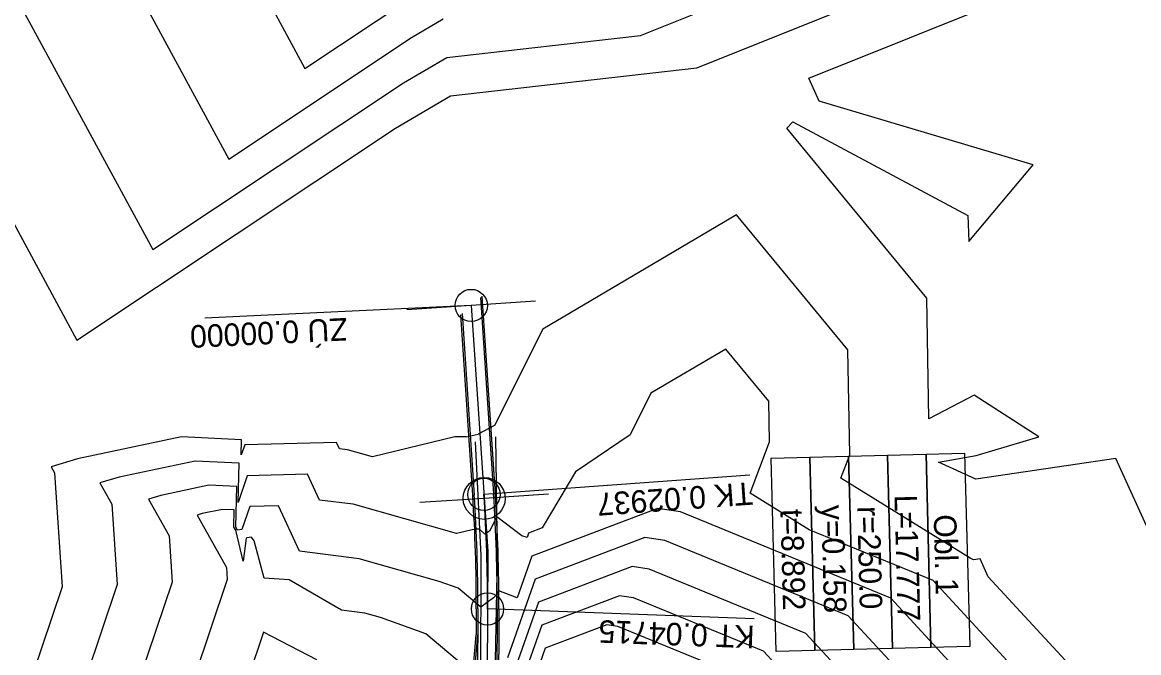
# Model space of a CAD drawing. Extents: x -549394 to -546608, y -1037055 to -1033629.
# Drawn here: x -547510.8 to -547337.6, y -1035891.5 to -1035793.8 of the extents above; entities that cross this region are included whole.
import ezdxf

# ---------------------------------------------------------------- set-up
doc = ezdxf.new("R2010")
doc.units = 0
for name, color, linetype in [('hlavni_vrst', 7, 'Continuous'), ('hrana_L', 7, 'Continuous'), ('norm_vrst', 7, 'Continuous'), ('POLYGONY_SITUACE_PO', 7, 'Continuous'), ('u_sirka_1_5m', 7, 'Continuous'), ('x_navrh_C41', 7, 'Continuous'), ('x_osa_C41', 7, 'Continuous'), ('x_popis_oblouky_C41', 7, 'Continuous'), ('x_popis_pricne_rezy_C41', 7, 'Continuous')]:
    doc.layers.add(name, color=color, linetype=linetype)

msp = doc.modelspace()

# ---------------------------------------------------------------- linework, layer by layer
at = {"layer": 'hlavni_vrst'}
for p, q in [((-547406.17, -1035800.86), (-547360.49, -1035782.56)), ((-547532.66, -1035787.02), (-547502.28, -1035843.08)), ((-547444.33, -1035805.2), (-547406.17, -1035800.86)), ((-547452.88, -1035810.18), (-547444.33, -1035805.2)), ((-547502.28, -1035843.08), (-547452.88, -1035810.18)), ((-547399.98, -1035823.64), (-547430.05, -1035841.36)), ((-547382.73, -1035844.56), (-547399.98, -1035823.64)), ((-547430.05, -1035841.36), (-547437.54, -1035856.34)), ((-547382.44, -1035860.87), (-547382.73, -1035844.56)), ((-547441.94, -1035858.1), (-547440.06, -1035857.66)), ((-547437.54, -1035856.34), (-547440.06, -1035857.66)), ((-547486.09, -1035858.1), (-547502.18, -1035861.49)), ((-547476.76, -1035858.54), (-547486.09, -1035858.1)), ((-547476.83, -1035860.89), (-547476.76, -1035858.54)), ((-547476.27, -1035859.29), (-547476.83, -1035860.89)), ((-547462.05, -1035858.96), (-547476.27, -1035859.29)), ((-547461.59, -1035859.93), (-547462.05, -1035858.96)), ((-547443.69, -1035858.08), (-547456.44, -1035861.2)), ((-547441.94, -1035858.1), (-547443.69, -1035858.08)), ((-547460.32, -1035860.09), (-547461.59, -1035859.93)), ((-547456.44, -1035861.2), (-547460.32, -1035860.09)), ((-547383.82, -1035864.47), (-547382.44, -1035860.87)), ((-547502.18, -1035861.49), (-547506.27, -1035862.72)), ((-547506.27, -1035862.72), (-547505.76, -1035863.64)), ((-547505.76, -1035863.64), (-547504.58, -1035881.36)), ((-547363.77, -1035876.89), (-547383.82, -1035864.47)), ((-547363.25, -1035877.13), (-547363.77, -1035876.89)), ((-547362.22, -1035876.97), (-547363.25, -1035877.13)), ((-547360.95, -1035879.77), (-547362.22, -1035876.97)), ((-547332, -1035911.09), (-547360.95, -1035879.77)), ((-547504.58, -1035881.36), (-547509.38, -1035895.62)), ((-547418.16, -1035882.71), (-547430.19, -1035887.28)), ((-547415.96, -1035883.04), (-547418.16, -1035882.71)), ((-547395.81, -1035891.3), (-547415.96, -1035883.04)), ((-547430.19, -1035887.28), (-547434.32, -1035898.99)), ((-547380.57, -1035907.78), (-547395.81, -1035891.3))]:
    msp.add_line(p, q, dxfattribs=at)
at = {"layer": 'hrana_L'}
for p, q in [((-547440.53, -1035858.83), (-547439.64, -1035876.54)), ((-547437.07, -1035876.65), (-547437.31, -1035858.07)), ((-547439.64, -1035876.54), (-547439.76, -1035904.44)), ((-547437.57, -1035904.54), (-547437.07, -1035876.65))]:
    msp.add_line(p, q, dxfattribs=at)
at = {"layer": 'norm_vrst'}
for p, q in [((-547557.48, -1035705.44), (-547490.5, -1035829.04)), ((-547531.65, -1035717.32), (-547478.72, -1035814.99)), ((-547500.19, -1035739.58), (-547466.93, -1035800.95)), ((-547414.88, -1035795.82), (-547378.94, -1035781.42)), ((-547388.81, -1035802.44), (-547342.04, -1035783.7)), ((-547466.93, -1035800.95), (-547449.13, -1035789.09)), ((-547450.38, -1035796.12), (-547445.48, -1035793.26)), ((-547478.72, -1035814.99), (-547450.38, -1035796.12)), ((-547444.91, -1035799.23), (-547414.88, -1035795.82)), ((-547451.63, -1035803.15), (-547444.91, -1035799.23)), ((-547387.2, -1035806.02), (-547388.81, -1035802.44)), ((-547490.5, -1035829.04), (-547451.63, -1035803.15)), ((-547354.01, -1035815.88), (-547387.2, -1035806.02)), ((-547392.21, -1035810.2), (-547391.27, -1035809.21)), ((-547391.27, -1035809.21), (-547364.11, -1035823.77)), ((-547370.48, -1035836.56), (-547392.21, -1035810.2)), ((-547363.98, -1035827.76), (-547354.01, -1035815.88)), ((-547364.11, -1035823.77), (-547363.98, -1035827.76)), ((-547370.15, -1035855.29), (-547370.48, -1035836.56)), ((-547401.65, -1035844.47), (-547413.27, -1035851.32)), ((-547394.98, -1035852.56), (-547401.65, -1035844.47)), ((-547413.27, -1035851.32), (-547416.5, -1035857.79)), ((-547394.87, -1035858.87), (-547394.98, -1035852.56)), ((-547363.17, -1035851.61), (-547370.15, -1035855.29)), ((-547353.11, -1035858.1), (-547363.17, -1035851.61)), ((-547416.5, -1035857.79), (-547424.96, -1035863.5)), ((-547397.89, -1035866.8), (-547394.87, -1035858.87)), ((-547362.82, -1035860.98), (-547353.11, -1035858.1)), ((-547368.68, -1035861.98), (-547362.82, -1035860.98)), ((-547483.96, -1035861.84), (-547495.74, -1035864.32)), ((-547477.14, -1035862.16), (-547483.96, -1035861.84)), ((-547477.3, -1035868.25), (-547477.14, -1035862.16)), ((-547362.9, -1035864.64), (-547368.68, -1035861.98)), ((-547341.16, -1035861.46), (-547362.9, -1035864.64)), ((-547324.65, -1035897.88), (-547341.16, -1035861.46)), ((-547495.74, -1035864.32), (-547498.73, -1035865.22)), ((-547475.87, -1035864.1), (-547477.3, -1035868.25)), ((-547466.55, -1035863.88), (-547475.87, -1035864.1)), ((-547464.67, -1035867.88), (-547466.55, -1035863.88)), ((-547424.96, -1035863.5), (-547430.12, -1035872.21)), ((-547498.73, -1035865.22), (-547496.88, -1035868.54)), ((-547481.83, -1035865.58), (-547489.29, -1035867.15)), ((-547477.51, -1035865.78), (-547481.83, -1035865.58)), ((-547477.67, -1035872.07), (-547477.51, -1035865.78)), ((-547489.29, -1035867.15), (-547491.19, -1035867.72)), ((-547491.19, -1035867.72), (-547487.99, -1035873.45)), ((-547459.43, -1035868.53), (-547464.67, -1035867.88)), ((-547388.73, -1035872.48), (-547397.89, -1035866.8)), ((-547496.88, -1035868.54), (-547496.05, -1035880.98)), ((-547482.85, -1035869.98), (-547483.65, -1035870.22)), ((-547479.7, -1035869.32), (-547482.85, -1035869.98)), ((-547477.88, -1035869.41), (-547479.7, -1035869.32)), ((-547477.95, -1035872.06), (-547477.88, -1035869.41)), ((-547475.46, -1035868.9), (-547476.69, -1035872.47)), ((-547471.05, -1035868.8), (-547475.46, -1035868.9)), ((-547467.75, -1035875.83), (-547471.05, -1035868.8)), ((-547443.42, -1035873.09), (-547459.43, -1035868.53)), ((-547412.27, -1035869.19), (-547431.73, -1035876.58)), ((-547408.71, -1035869.72), (-547412.27, -1035869.19)), ((-547376.09, -1035883.09), (-547408.71, -1035869.72)), ((-547483.65, -1035870.22), (-547479.11, -1035878.36)), ((-547437.15, -1035870.5), (-547438.29, -1035872.68)), ((-547433.28, -1035873.42), (-547437.15, -1035870.5)), ((-547487.99, -1035873.45), (-547487.52, -1035880.6)), ((-547477.66, -1035872.55), (-547477.95, -1035872.06)), ((-547477.4, -1035872.53), (-547477.67, -1035872.07)), ((-547476.49, -1035877.36), (-547477.66, -1035872.55)), ((-547476.69, -1035872.47), (-547477.4, -1035872.53)), ((-547440.55, -1035872.39), (-547443.42, -1035873.09)), ((-547439.85, -1035872.4), (-547440.55, -1035872.39)), ((-547439.04, -1035873.18), (-547439.85, -1035872.4)), ((-547438.29, -1035872.68), (-547439.04, -1035873.18)), ((-547432.49, -1035873.71), (-547433.28, -1035873.42)), ((-547432.25, -1035873.02), (-547432.49, -1035873.71)), ((-547430.12, -1035872.21), (-547432.25, -1035873.02)), ((-547369.51, -1035880.35), (-547388.73, -1035872.48)), ((-547476.05, -1035873.78), (-547476.49, -1035877.36)), ((-547475.95, -1035873.74), (-547476.05, -1035873.78)), ((-547475.2, -1035873.61), (-547475.95, -1035873.74)), ((-547474.8, -1035874.21), (-547475.2, -1035873.61)), ((-547473.24, -1035879.97), (-547474.8, -1035874.21)), ((-547414.23, -1035873.7), (-547431.22, -1035880.15)), ((-547411.13, -1035874.16), (-547414.23, -1035873.7)), ((-547382.66, -1035885.83), (-547411.13, -1035874.16)), ((-547458.53, -1035876.97), (-547467.75, -1035875.83)), ((-547446.11, -1035880.51), (-547458.53, -1035876.97)), ((-547431.73, -1035876.58), (-547434.01, -1035883.03)), ((-547479.11, -1035878.36), (-547478.99, -1035880.21)), ((-547416.2, -1035878.21), (-547430.7, -1035883.72)), ((-547413.54, -1035878.6), (-547416.2, -1035878.21)), ((-547389.24, -1035888.56), (-547413.54, -1035878.6)), ((-547478.99, -1035880.21), (-547488.68, -1035908.97)), ((-547469.38, -1035880.26), (-547473.24, -1035879.97)), ((-547461.27, -1035884.97), (-547469.38, -1035880.26)), ((-547431.22, -1035880.15), (-547435.53, -1035892.36)), ((-547341.71, -1035910.43), (-547369.51, -1035880.35)), ((-547496.05, -1035880.98), (-547502.48, -1035900.07)), ((-547487.52, -1035880.6), (-547495.58, -1035904.52)), ((-547443.18, -1035881.56), (-547446.11, -1035880.51)), ((-547439.67, -1035884.5), (-547443.18, -1035881.56)), ((-547436.88, -1035881.96), (-547437.18, -1035882.52)), ((-547434.01, -1035883.03), (-547436.88, -1035881.96)), ((-547437.69, -1035883.03), (-547439.67, -1035884.5)), ((-547437.18, -1035882.52), (-547437.69, -1035883.03)), ((-547430.7, -1035883.72), (-547435.69, -1035897.84)), ((-547351.43, -1035909.77), (-547376.09, -1035883.09)), ((-547457.64, -1035885.41), (-547461.27, -1035884.97)), ((-547455.23, -1035886.1), (-547457.64, -1035885.41)), ((-547448.18, -1035888.64), (-547455.23, -1035886.1)), ((-547420.13, -1035887.22), (-547429.67, -1035890.85)), ((-547418.38, -1035887.48), (-547420.13, -1035887.22)), ((-547361.14, -1035909.11), (-547382.66, -1035885.83)), ((-547473.34, -1035888.39), (-547481.77, -1035913.42)), ((-547465.08, -1035892.66), (-547473.34, -1035888.39)), ((-547439.72, -1035895.7), (-547448.18, -1035888.64)), ((-547402.38, -1035894.04), (-547418.38, -1035887.48)), ((-547370.86, -1035908.45), (-547389.24, -1035888.56)), ((-547429.67, -1035890.85), (-547432.95, -1035900.15))]:
    msp.add_line(p, q, dxfattribs=at)
at = {"layer": 'POLYGONY_SITUACE_PO'}
for centre in [(-547441.14, -1035837.7), (-547439.17, -1035867.01), (-547438.62, -1035884.77)]:
    msp.add_circle(centre, 2.5, dxfattribs=at)
at = {"layer": 'u_sirka_1_5m'}
msp.add_circle((-547439.13, -1035867.63), 3.25, dxfattribs=at)
at = {"layer": 'x_navrh_C41'}
for p, q in [((-547439.71, -1035836.47), (-547437.68, -1035866.91)), ((-547442.56, -1035838.93), (-547440.67, -1035867.11)), ((-547440.12, -1035884.76), (-547440.18, -1035898.77)), ((-547437.12, -1035884.78), (-547437.18, -1035898.78)), ((-547441.22, -1035898.76), (-547440.38, -1035888.76)), ((-547440.97, -1035898.77), (-547440.13, -1035888.77))]:
    msp.add_line(p, q, dxfattribs=at)
for points in [[(-547439.48, -1035836.26), (-547437.43, -1035866.89)], [(-547442.79, -1035839.14), (-547440.92, -1035867.12)], [(-547440.37, -1035884.76), (-547440.38, -1035888.76)], [(-547436.87, -1035884.78), (-547436.93, -1035898.79)]]:
    msp.add_lwpolyline(points, dxfattribs=at)
for radius in [248.25, 248.5, 251.5, 251.75]:
    msp.add_arc((-547688.61, -1035883.7), radius, 359.756, 3.8301, dxfattribs=at)
at = {"layer": 'x_osa_C41'}
msp.add_lwpolyline([(-547441.14, -1035837.7), (-547438.58, -1035875.88), (-547438.7, -1035904.25), (-547453.65, -1035956.98)], dxfattribs=at)
msp.add_arc((-547688.61, -1035883.7), 250, 359.756, 3.8301, dxfattribs=at)
at = {"layer": 'x_popis_oblouky_C41'}
for points in [[(-547441.14, -1035837.7), (-547482.46, -1035839.69)], [(-547397.91, -1035864.03), (-547439.17, -1035867.01)], [(-547397.27, -1035886.29), (-547438.62, -1035884.77)]]:
    msp.add_lwpolyline(points, dxfattribs=at)
for points in [[(-547388.61, -1035861.22), (-547387.83, -1035891.21), (-547393.83, -1035891.37), (-547394.61, -1035861.38)], [(-547382.61, -1035861.06), (-547381.83, -1035891.05), (-547387.83, -1035891.21), (-547388.61, -1035861.22)], [(-547376.61, -1035860.91), (-547375.83, -1035890.9), (-547381.83, -1035891.05), (-547382.61, -1035861.06)], [(-547370.61, -1035860.75), (-547369.84, -1035890.74), (-547375.83, -1035890.9), (-547376.61, -1035860.91)], [(-547364.62, -1035860.6), (-547363.84, -1035890.59), (-547369.84, -1035890.74), (-547370.61, -1035860.75)]]:
    msp.add_lwpolyline(points, close=True, dxfattribs=at)
at = {"layer": 'x_popis_pricne_rezy_C41'}
for points in [[(-547431.16, -1035837.03), (-547441.14, -1035837.7), (-547451.11, -1035838.37)], [(-547429.15, -1035866.99), (-547439.13, -1035867.63), (-547449.11, -1035868.28)]]:
    msp.add_lwpolyline(points, dxfattribs=at)

# ---------------------------------------------------------------- texts
at = {"layer": 'x_popis_oblouky_C41'}
for s, rotation, p in [('ZÚ 0.00000', 182.7509, (-547460.4, -1035839.62)), ('TK 0.02937', 184.1284, (-547397.61, -1035865.09)), ('L=17.777', 271.5097, (-547375.51, -1035867.09)), ('t=8.892', 271.5097, (-547393.19, -1035869.3)), ('y=0.158', 271.5097, (-547386.86, -1035868.67)), ('r=250.0', 271.5097, (-547381.29, -1035868.87)), ('Obl. 1', 271.5097, (-547369.42, -1035870.14)), ('KT 0.04715', 177.8934, (-547397.13, -1035887.38))]:
    msp.add_text(s, height=3.5, rotation=rotation, dxfattribs=at).set_placement(p)

doc.saveas('drawing.dxf')
